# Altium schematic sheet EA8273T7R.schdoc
size 127 x 101 mm
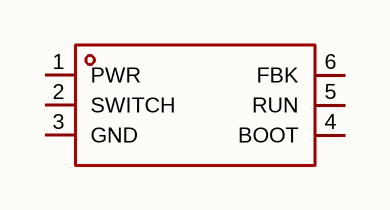
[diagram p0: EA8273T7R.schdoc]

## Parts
U?  ea8273t7r  [SOT-563-6_L1.6-W1.2-P0.50-LS1.6-BL]  (value not drawn)

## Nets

Not connected (* = marked no-connect by the designer): U? 1(PWR) 2(SWITCH) 3(GND) 4(BOOT) 5(RUN) 6(FBK)

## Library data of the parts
U? = ea8273t7r: 功能类型:降压型;工作电压:4.5V~16V;输出电压:600mV~9V;输出电流:3A;输出类型:可调;; Manufacturer: everanalog(申风); AddInBom: yes; ModelId: 03ffed36a9f44d3f8e9b9d03c9339c51; ModelTransform: 62.992,62.992,0,0,0,0,0,0,0; Function: 降压型; Output Current: 3A; Frequency - Switching: 600kHz; Synchronous Rectifier: 是; Number of Outputs: 1; Topology: 降压式; Quiescent Current: 350uA; Switch tube (built-in/external): 内置; Output Type: 可调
